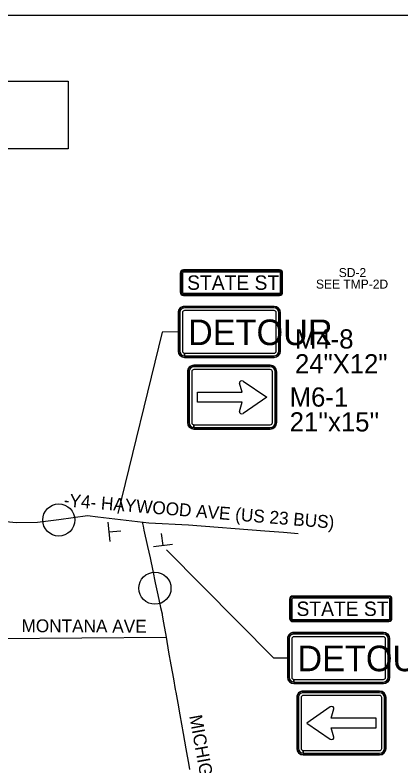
# Model space of a CAD drawing. Extents: x 886234 to 968767, y 455416 to 684046.
# Drawn here: x 925200 to 928577, y 482607 to 489183 of the extents above; entities that cross this region are included whole.
import ezdxf

# ---------------------------------------------------------------- set-up
doc = ezdxf.new("R2010")
doc.units = 0
for name, color, linetype in [('Scratch_Level_3', 7, 'Continuous'), ('TC DEV SIGN', 7, 'Continuous'), ('TC DEV SIGN BLACK 239', 7, 'Continuous'), ('TC DEV SIGN BLACK ZERO', 7, 'Continuous'), ('TC DEV SIGN ORANGE', 7, 'Continuous'), ('TC DEV SIGN WHITE', 7, 'Continuous'), ('TC LABEL TEXT', 7, 'Continuous')]:
    doc.layers.add(name, color=color, linetype=linetype)

msp = doc.modelspace()

# ---------------------------------------------------------------- linework, layer by layer
at = {"layer": 'Scratch_Level_3'}
msp.add_line((904674.3, 489183.5), (936553.3, 489183.5), dxfattribs=at)
at = {"layer": 'TC DEV SIGN'}
for p, q in [((926013.2, 484740.4), (926029.6, 484571.4)), ((926021.4, 484655.9), (926126.2, 484666.1)), ((926495.1, 484538.8), (926481.9, 484643.2)), ((926410.8, 484528.1), (926579.3, 484549.4))]:
    msp.add_line(p, q, dxfattribs=at)
at = {"layer": 'TC DEV SIGN BLACK 239'}
for p, q in [((926722.7, 486059.3), (926722.6, 485614.1)), ((926746.3, 486059.3), (926746.3, 485614.1)), ((927433.1, 486101.9), (926765.3, 486101.9)), ((927433.1, 486078.3), (926765.3, 486078.3)), ((927452, 485614.1), (927452, 486059.3)), ((927475.7, 485614.1), (927475.7, 486059.3)), ((927196.7, 485977.2), (927402, 485835.8)), ((927187.8, 485879.4), (927164.6, 485960)), ((926795.9, 485793.6), (926795.9, 485879.4)), ((926795.9, 485879.4), (927187.8, 485879.4)), ((927187.7, 485793.6), (926795.9, 485793.6)), ((927164.6, 485711.6), (927187.7, 485793.6)), ((927402, 485835.8), (927196.7, 485694.4)), ((926765.2, 485571.5), (926765.2, 485595.1)), ((926765.5, 485595.1), (927433.1, 485595.1)), ((926765.5, 485595.1), (926765.5, 485571.5)), ((926765.5, 485571.5), (927433.1, 485571.5)), ((928389.8, 483248.3), (927721.9, 483248.3)), ((928389.8, 483224.6), (927721.9, 483224.6)), ((927679.3, 483205.7), (927679.3, 482760.4)), ((927703, 483205.7), (927703, 482760.4)), ((928408.7, 482760.4), (928408.7, 483205.7)), ((928432.4, 482760.4), (928432.4, 483205.7)), ((927958.4, 483123.5), (927753.1, 482982.1)), ((927967.3, 483025.7), (927990.4, 483106.3)), ((928359.1, 483025.7), (927967.3, 483025.7)), ((928359.1, 482940), (928359.1, 483025.7)), ((927753.1, 482982.1), (927958.4, 482840.7)), ((927990.4, 482857.9), (927967.3, 482940)), ((927967.3, 482940), (928359.1, 482940)), ((927721.9, 482717.8), (927721.9, 482741.5)), ((927722.2, 482741.5), (928389.8, 482741.5)), ((927722.2, 482741.5), (927722.2, 482717.8)), ((927722.2, 482717.8), (928389.8, 482717.8))]:
    msp.add_line(p, q, dxfattribs=at)
for centre, major_axis, ratio, start_param, end_param in [((926765.3, 486059.3), (42.6, 0), 0.999865, 1.570796, 3.141593), ((926765.3, 486059.3), (18.9, 0), 0.999865, 1.570796, 3.141593), ((927433.1, 486059.3), (42.6, 0), 0.999865, 0, 1.570796), ((927433.1, 486059.3), (18.9, 0), 0.999865, 0, 1.570796), ((927184.7, 485964.6), (21.1, 0), 0.720018, 0.96961, 3.452569), ((927184.7, 485706.9), (21.1, 0), 0.720018, 2.830617, 5.313577), ((926765.2, 485614.1), (42.6, 0), 0.999865, 3.141593, 4.712389), ((926765.2, 485614.1), (18.9, 0), 0.999865, 3.141593, 4.712389), ((927433.1, 485614.1), (42.6, 0), 0.999865, 4.712389, 6.283185), ((927433.1, 485614.1), (18.9, 0), 0.999865, 4.712389, 6.283185), ((927721.9, 483205.7), (42.6, 0), 0.999865, 1.570796, 3.141593), ((927721.9, 483205.7), (18.9, 0), 0.999865, 1.570796, 3.141593), ((928389.8, 483205.7), (42.6, 0), 0.999865, 0, 1.570796), ((928389.8, 483205.7), (18.9, 0), 0.999865, 0, 1.570796), ((927970.3, 483111), (-21.1, 0), 0.720018, 2.830616, 5.313575), ((927970.3, 482853.3), (-21.1, 0), 0.720018, 0.969609, 3.452568), ((927721.9, 482760.4), (42.6, 0), 0.999865, 3.141593, 4.712389), ((927721.9, 482760.4), (18.9, 0), 0.999865, 3.141593, 4.712389), ((928389.8, 482760.4), (42.6, 0), 0.999865, 4.712389, 6.283185), ((928389.8, 482760.4), (18.9, 0), 0.999865, 4.712389, 6.283185)]:
    msp.add_ellipse(centre, major_axis=major_axis, ratio=ratio, start_param=start_param, end_param=end_param, dxfattribs=at)
at = {"layer": 'TC DEV SIGN BLACK ZERO'}
for p, q in [((926645.5, 486923.4), (926645.5, 486755.4)), ((926646.6, 486923.4), (926646.6, 486755.4)), ((926646.6, 486923.4), (926646.6, 486923.4)), ((926652.5, 486923.4), (926652.5, 486755.4)), ((926664.1, 486923.4), (926664.1, 486755.4)), ((927513.5, 486951.3), (926673.5, 486951.4)), ((926673.5, 486950.2), (926673.5, 486950.2)), ((927513.5, 486950.2), (926673.5, 486950.2)), ((927513.5, 486944.3), (926673.5, 486944.4)), ((927513.5, 486932.7), (926673.5, 486932.7)), ((927513.5, 486950.2), (927513.5, 486950.2)), ((927522.8, 486755.5), (927522.8, 486923.3)), ((927534.5, 486755.5), (927534.5, 486923.3)), ((927540.3, 486923.3), (927540.3, 486923.3)), ((927540.3, 486755.4), (927540.3, 486923.3)), ((927541.5, 486755.4), (927541.5, 486923.3)), ((926646.6, 486755.4), (926646.6, 486755.4)), ((926673.5, 486746), (927513.5, 486746)), ((926673.5, 486734.4), (927513.5, 486734.3)), ((926673.5, 486728.5), (927513.5, 486728.5)), ((926673.5, 486728.5), (926673.5, 486728.5)), ((926673.5, 486727.4), (927513.5, 486727.3)), ((927513.5, 486728.5), (927513.5, 486728.5)), ((927522.8, 486755.5), (927534.5, 486755.5)), ((927534.5, 486755.3), (927522.8, 486755.3)), ((927540.3, 486755.4), (927541.5, 486755.4)), ((927541.5, 486755.3), (927540.3, 486755.3)), ((927540.3, 486755.3), (927540.3, 486755.3)), ((927467.1, 486632), (926683, 486632)), ((926683, 486629.7), (926683, 486629.7)), ((927467.1, 486629.7), (926683, 486629.7)), ((927467.1, 486629.7), (927467.1, 486629.7)), ((926627, 486576), (926627, 486240)), ((926629.3, 486576), (926629.3, 486240)), ((926629.3, 486576), (926629.4, 486576)), ((926641, 486576), (926641, 486240)), ((926664.4, 486576), (926664.4, 486240)), ((927467.1, 486618), (926683, 486618)), ((927467.1, 486594.7), (926683, 486594.7)), ((927485.8, 486240), (927485.8, 486576)), ((927509.1, 486240), (927509.1, 486576)), ((927520.8, 486576), (927520.8, 486576)), ((927520.8, 486240), (927520.8, 486576)), ((927523.1, 486240), (927523.1, 486576)), ((926629.4, 486240), (926629.3, 486240)), ((927520.8, 486240), (927520.8, 486240)), ((926683, 486198), (926683, 486221.4)), ((926683, 486184), (926683, 486186.4)), ((926683, 486186.4), (926683, 486186.4)), ((926683.1, 486186.4), (927467.1, 486186.4)), ((926683.1, 486186.4), (926683.1, 486184)), ((926683.1, 486184), (927467.1, 486184)), ((926683.3, 486221.4), (927467.1, 486221.4)), ((926683.3, 486221.4), (926683.3, 486198)), ((926683.3, 486198), (927467.1, 486198)), ((927467.1, 486186.4), (927467.1, 486186.4)), ((927433.1, 486116.1), (926765.3, 486116.1)), ((926765.3, 486113.8), (926765.3, 486113.8)), ((927433.1, 486113.7), (926765.3, 486113.8)), ((927433.1, 486113.7), (927433.1, 486113.8)), ((926708.5, 486059.3), (926708.4, 485614.1)), ((926710.8, 486059.3), (926710.8, 485614.1)), ((926710.8, 486059.3), (926710.8, 486059.3)), ((927487.5, 486059.3), (927487.6, 486059.3)), ((927487.5, 485614.1), (927487.6, 486059.3)), ((927489.9, 485614.1), (927489.9, 486059.3)), ((926710.8, 485614.1), (926710.8, 485614.1)), ((927487.5, 485614.1), (927487.5, 485614.1)), ((926765.2, 485557.3), (926765.2, 485559.6)), ((926765.2, 485559.6), (926765.2, 485559.6)), ((926765.3, 485559.6), (927433.1, 485559.6)), ((926765.3, 485559.6), (926765.3, 485557.3)), ((926765.3, 485557.3), (927433.1, 485557.3)), ((927433.1, 485559.6), (927433.1, 485559.6)), ((927602.4, 484067.2), (927602.4, 483899.2)), ((927603.6, 484067.2), (927603.6, 483899.2)), ((927603.6, 484067.2), (927603.6, 484067.2)), ((927609.4, 484067.2), (927609.4, 483899.2)), ((927621.1, 484067.2), (927621.1, 483899.2)), ((928470.4, 484095.2), (927630.4, 484095.2)), ((927630.4, 484094), (927630.4, 484094)), ((928470.4, 484094), (927630.4, 484094)), ((928470.4, 484088.2), (927630.4, 484088.2)), ((928470.4, 484076.5), (927630.4, 484076.5)), ((928470.4, 484094), (928470.4, 484094)), ((928479.7, 483899.3), (928479.7, 484067.2)), ((928491.4, 483899.3), (928491.4, 484067.2)), ((928497.2, 484067.2), (928497.2, 484067.2)), ((928497.2, 483899.2), (928497.2, 484067.2)), ((928498.4, 483899.2), (928498.4, 484067.2)), ((927603.6, 483899.2), (927603.6, 483899.2)), ((927630.4, 483889.9), (928470.4, 483889.8)), ((927630.4, 483878.2), (928470.4, 483878.2)), ((927630.4, 483872.3), (927630.4, 483872.4)), ((927630.4, 483872.3), (928470.4, 483872.3)), ((927630.4, 483871.2), (928470.4, 483871.2)), ((928470.4, 483872.3), (928470.4, 483872.3)), ((928479.7, 483899.3), (928491.4, 483899.3)), ((928491.4, 483899.2), (928479.7, 483899.2)), ((928498.4, 483899.2), (928497.2, 483899.2)), ((928497.2, 483899.2), (928497.2, 483899.2)), ((928497.2, 483899.2), (928498.4, 483899.2)), ((928424.1, 483775.9), (927640, 483775.9)), ((927640, 483773.5), (927640, 483773.5)), ((928424.1, 483773.5), (927640, 483773.5)), ((928424.1, 483761.9), (927640, 483761.9)), ((928424.1, 483738.5), (927640, 483738.5)), ((928424.1, 483773.5), (928424.1, 483773.5)), ((927584, 483719.9), (927584, 483383.9)), ((927586.3, 483719.9), (927586.3, 483383.9)), ((927586.3, 483719.9), (927586.3, 483719.9)), ((927598, 483719.9), (927598, 483383.9)), ((927621.3, 483719.9), (927621.3, 483383.9)), ((928442.8, 483383.9), (928442.8, 483719.9)), ((928466.1, 483383.9), (928466.1, 483719.9)), ((928477.8, 483719.9), (928477.8, 483719.9)), ((928477.8, 483383.9), (928477.8, 483719.9)), ((928480.1, 483383.9), (928480.1, 483719.9)), ((927586.3, 483383.9), (927586.3, 483383.9)), ((927640, 483341.9), (927640, 483365.2)), ((927640.2, 483365.2), (928424.1, 483365.2)), ((927640.2, 483365.2), (927640.2, 483341.9)), ((927640.2, 483341.9), (928424.1, 483341.9)), ((928477.8, 483383.9), (928477.8, 483383.9)), ((927640, 483327.9), (927640, 483330.2)), ((927640, 483330.2), (927640, 483330.2)), ((927640, 483330.2), (928424.1, 483330.2)), ((927640, 483330.2), (927640, 483327.9)), ((927640, 483327.9), (928424.1, 483327.9)), ((928424.1, 483330.2), (928424.1, 483330.2)), ((928389.8, 483262.5), (927721.9, 483262.5)), ((927721.9, 483260.1), (927721.9, 483260.1)), ((928389.8, 483260.1), (927721.9, 483260.1)), ((928389.8, 483260.1), (928389.8, 483260.1)), ((927665.1, 483205.7), (927665.1, 482760.4)), ((927667.5, 483205.7), (927667.5, 482760.4)), ((927667.5, 483205.7), (927667.5, 483205.7)), ((928444.2, 483205.7), (928444.2, 483205.7)), ((928444.2, 482760.4), (928444.2, 483205.7)), ((928446.6, 482760.4), (928446.6, 483205.7)), ((927667.5, 482760.4), (927667.5, 482760.4)), ((928444.2, 482760.4), (928444.2, 482760.4)), ((927721.9, 482703.6), (927721.9, 482706)), ((927721.9, 482706), (927721.9, 482706)), ((927722, 482706), (928389.8, 482706)), ((927722, 482706), (927722, 482703.6)), ((927722, 482703.6), (928389.8, 482703.6)), ((928389.8, 482706), (928389.8, 482706))]:
    msp.add_line(p, q, dxfattribs=at)
for centre, major_axis, start_param, end_param in [((926673.5, 486923.4), (0, 28), 0, 1.570796), ((926673.5, 486923.4), (0, 26.8), 0, 1.570796), ((926673.5, 486923.4), (0, 21), 0, 1.570796), ((926673.5, 486923.4), (0, 9.33), 0, 1.570796), ((927513.5, 486923.3), (0, 28), 4.712389, 6.283185), ((927513.5, 486923.3), (0, 26.8), 4.712389, 6.283185), ((927513.5, 486923.3), (0, 21), 4.712389, 6.283185), ((927513.5, 486923.3), (0, 9.33), 4.712389, 6.283185), ((926673.5, 486755.4), (0, 28), 1.570796, 3.141593), ((926673.5, 486755.4), (0, 26.8), 1.570796, 3.141593), ((926673.5, 486755.4), (0, 21), 1.570796, 3.141593), ((926673.5, 486755.4), (0, 9.33), 1.570796, 3.141593), ((927513.5, 486755.3), (0, 21), 3.141593, 4.712389), ((927513.5, 486755.3), (0, 9.33), 3.141593, 4.712389), ((927513.5, 486755.3), (0, 28), 3.141593, 4.712389), ((927513.5, 486755.3), (0, 26.8), 3.141593, 4.712389), ((926683, 486576), (56, 0), 1.570796, 3.141593), ((926683, 486576), (53.7, 0), 1.570796, 3.141593), ((927467.1, 486576), (56, 0), 0, 1.570796), ((927467.1, 486576), (53.7, 0), 0, 1.570796), ((926683, 486576), (42, 0), 1.570796, 3.141593), ((926683, 486576), (18.7, 0), 1.570796, 3.141593), ((927467.1, 486576), (42, 0), 0, 1.570796), ((927467.1, 486576), (18.7, 0), 0, 1.570796), ((926683, 486240), (56, 0), 3.141593, 4.712389), ((926683, 486240), (53.7, 0), 3.141593, 4.712389), ((926683, 486240), (42, 0), 3.141593, 4.712389), ((926683, 486240), (18.7, 0), 3.141593, 4.712389), ((927467.1, 486240), (42, 0), 4.712389, 6.283185), ((927467.1, 486240), (18.7, 0), 4.712389, 6.283185), ((927467.1, 486240), (56, 0), 4.712389, 6.283185), ((927467.1, 486240), (53.7, 0), 4.712389, 6.283185), ((926765.3, 486059.3), (56.8, 0), 1.570796, 3.141593), ((926765.3, 486059.3), (54.4, 0), 1.570796, 3.141593), ((927433.1, 486059.3), (56.8, 0), 0, 1.570796), ((927433.1, 486059.3), (54.4, 0), 0, 1.570796), ((926765.2, 485614.1), (56.8, 0), 3.141593, 4.712389), ((926765.2, 485614.1), (54.4, 0), 3.141593, 4.712389), ((927433.1, 485614.1), (56.8, 0), 4.712389, 6.283185), ((927433.1, 485614.1), (54.4, 0), 4.712389, 6.283185), ((927630.4, 484067.2), (0, 28), 0, 1.570796), ((927630.4, 484067.2), (0, 26.8), 0, 1.570796), ((927630.4, 484067.2), (0, 21), 0, 1.570796), ((927630.4, 484067.2), (0, 9.33), 0, 1.570796), ((928470.4, 484067.2), (0, 28), 4.712389, 6.283185), ((928470.4, 484067.2), (0, 26.8), 4.712389, 6.283185), ((928470.4, 484067.2), (0, 21), 4.712389, 6.283185), ((928470.4, 484067.2), (0, 9.33), 4.712389, 6.283185), ((927630.4, 483899.2), (0, 28), 1.570796, 3.141593), ((927630.4, 483899.2), (0, 26.8), 1.570796, 3.141593), ((927630.4, 483899.2), (0, 21), 1.570796, 3.141593), ((927630.4, 483899.2), (0, 9.33), 1.570796, 3.141593), ((928470.4, 483899.2), (0, 21), 3.141593, 4.712389), ((928470.4, 483899.2), (0, 9.33), 3.141593, 4.712389), ((928470.4, 483899.2), (0, 28), 3.141593, 4.712389), ((928470.4, 483899.2), (0, 26.8), 3.141593, 4.712389), ((927640, 483719.9), (56, 0), 1.570796, 3.141593), ((927640, 483719.9), (53.7, 0), 1.570796, 3.141593), ((927640, 483719.9), (42, 0), 1.570796, 3.141593), ((927640, 483719.9), (18.7, 0), 1.570796, 3.141593), ((928424.1, 483719.9), (56, 0), 0, 1.570796), ((928424.1, 483719.9), (53.7, 0), 0, 1.570796), ((928424.1, 483719.9), (42, 0), 0, 1.570796), ((928424.1, 483719.9), (18.7, 0), 0, 1.570796), ((927640, 483383.9), (56, 0), 3.141593, 4.712389), ((927640, 483383.9), (53.7, 0), 3.141593, 4.712389), ((927640, 483383.9), (42, 0), 3.141593, 4.712389), ((927640, 483383.9), (18.7, 0), 3.141593, 4.712389), ((928424.1, 483383.9), (42, 0), 4.712389, 6.283185), ((928424.1, 483383.9), (18.7, 0), 4.712389, 6.283185), ((928424.1, 483383.9), (56, 0), 4.712389, 6.283185), ((928424.1, 483383.9), (53.7, 0), 4.712389, 6.283185), ((927721.9, 483205.7), (56.8, 0), 1.570796, 3.141593), ((927721.9, 483205.7), (54.4, 0), 1.570796, 3.141593), ((928389.8, 483205.7), (56.8, 0), 0, 1.570796), ((928389.8, 483205.7), (54.4, 0), 0, 1.570796), ((927721.9, 482760.4), (56.8, 0), 3.141593, 4.712389), ((927721.9, 482760.4), (54.4, 0), 3.141593, 4.712389), ((928389.8, 482760.4), (56.8, 0), 4.712389, 6.283185), ((928389.8, 482760.4), (54.4, 0), 4.712389, 6.283185)]:
    msp.add_ellipse(centre, major_axis=major_axis, ratio=0.999865, start_param=start_param, end_param=end_param, dxfattribs=at)
at = {"layer": 'TC DEV SIGN ORANGE'}
for p, q in [((926645.5, 486923.4), (926645.5, 486755.4)), ((927513.5, 486951.3), (926673.5, 486951.4)), ((927541.5, 486755.3), (927541.5, 486923.3)), ((926673.5, 486727.4), (927513.5, 486727.3)), ((927467.1, 486632), (926683, 486632)), ((926627, 486576), (926627, 486240)), ((927523.1, 486240), (927523.1, 486576)), ((926683, 486184), (927467.1, 486184)), ((927602.4, 484067.2), (927602.4, 483899.2)), ((928470.4, 484095.2), (927630.4, 484095.2)), ((928498.4, 483899.2), (928498.4, 484067.2)), ((927630.4, 483871.2), (928470.4, 483871.2)), ((928424.1, 483775.9), (927640, 483775.9)), ((927584, 483719.9), (927584, 483383.9)), ((928480.1, 483383.9), (928480.1, 483719.9)), ((927640, 483327.9), (928424.1, 483327.9))]:
    msp.add_line(p, q, dxfattribs=at)
for centre, major_axis, start_param, end_param in [((926673.5, 486923.4), (0, 28), 0, 1.570796), ((927513.5, 486923.3), (0, 28), 4.712389, 6.283185), ((926673.5, 486755.4), (0, 28), 1.570796, 3.141593), ((927513.5, 486755.3), (0, 28), 3.141593, 4.712389), ((926683, 486576), (56, 0), 1.570796, 3.141593), ((927467.1, 486576), (56, 0), 0, 1.570796), ((926683, 486240), (56, 0), 3.141593, 4.712389), ((927467.1, 486240), (56, 0), 4.712389, 6.283185), ((927630.4, 484067.2), (0, 28), 0, 1.570796), ((928470.4, 484067.2), (0, 28), 4.712389, 6.283185), ((927630.4, 483899.2), (0, 28), 1.570796, 3.141593), ((928470.4, 483899.2), (0, 28), 3.141593, 4.712389), ((927640, 483719.9), (56, 0), 1.570796, 3.141593), ((928424.1, 483719.9), (56, 0), 0, 1.570796), ((927640, 483383.9), (56, 0), 3.141593, 4.712389), ((928424.1, 483383.9), (56, 0), 4.712389, 6.283185)]:
    msp.add_ellipse(centre, major_axis=major_axis, ratio=0.999865, start_param=start_param, end_param=end_param, dxfattribs=at)
at = {"layer": 'TC DEV SIGN WHITE'}
for p, q in [((927433.1, 486116.1), (926765.3, 486116.1)), ((926708.5, 486059.3), (926708.4, 485614.1)), ((927489.9, 485614.1), (927489.9, 486059.3)), ((926765.2, 485557.3), (927433.1, 485557.3)), ((928389.8, 483262.5), (927721.9, 483262.5)), ((927665.1, 483205.7), (927665.1, 482760.4)), ((928446.6, 482760.4), (928446.6, 483205.7)), ((927721.9, 482703.6), (928389.8, 482703.6))]:
    msp.add_line(p, q, dxfattribs=at)
for centre, start_param, end_param in [((926765.3, 486059.3), 1.570796, 3.141593), ((927433.1, 486059.3), 0, 1.570796), ((926765.2, 485614.1), 3.141593, 4.712389), ((927433.1, 485614.1), 4.712389, 6.283185), ((927721.9, 483205.7), 1.570796, 3.141593), ((928389.8, 483205.7), 0, 1.570796), ((927721.9, 482760.4), 3.141593, 4.712389), ((928389.8, 482760.4), 4.712389, 6.283185)]:
    msp.add_ellipse(centre, major_axis=(56.8, 0), ratio=0.999865, start_param=start_param, end_param=end_param, dxfattribs=at)
at = {"layer": 'TC LABEL TEXT'}
msp.add_line((925038.5, 483722.9), (926522.5, 483733.5), dxfattribs=at)
msp.add_lwpolyline([(921268.8, 488603.4), (925666, 488603.4), (925666, 488012.8), (921268.8, 488012.8)], close=True, dxfattribs=at)
for points in [[(926627, 486408), (926486.6, 486407.1), (926098.5, 484818)], [(927677.1, 484640.5), (927549.4, 484651), (927385, 484664.3), (926717, 484714.2), (926371, 484734.2), (925925.5, 484787), (925835.4, 484798.7), (925582.4, 484760.9), (925396.4, 484737.6), (925210.3, 484734.7), (925123.1, 484743.4), (924952.9, 484800)], [(926313.7, 484741), (926318, 484719.1), (926320.6, 484706.9), (926327.1, 484671.6), (926360.3, 484529.4), (926383.7, 484430), (926404.3, 484315.6), (926426.1, 484210.3), (926449.6, 484106.1), (926473.6, 483995.1), (926486.5, 483938.6), (926488.3, 483926.2)], [(927584, 483551.9), (927464, 483551.9), (926524.3, 484498.8)], [(926488.3, 483926.2), (926497.7, 483860.9), (926522.5, 483733.5), (926543.1, 483603), (926563.7, 483492.1), (926585.7, 483370.7), (926602.2, 483276.4), (926606.6, 483252.6)], [(926606.6, 483252.6), (926624.6, 483155.2), (926643.3, 483053.2), (926669.9, 482891.6), (926693.5, 482757.8), (926720, 482614.3), (926727.1, 482574.7)]]:
    msp.add_lwpolyline(points, dxfattribs=at)
for centre in [(925582.4, 484760.9), (925582.4, 484760.9), (926424.1, 484163.2), (926424.1, 484163.2)]:
    msp.add_circle(centre, 140.6, dxfattribs=at)

# ---------------------------------------------------------------- texts
at = {"layer": 'TC DEV SIGN BLACK ZERO'}
for s, height, p in [('STATE ST', 126, (926706.2, 486776.6)), ('DETOUR', 224, (926714.1, 486292.6)), ('STATE ST', 126, (927663.1, 483920.4)), ('DETOUR', 224, (927671.1, 483436.4))]:
    msp.add_text(s, height=height, dxfattribs=at).set_placement(p)
for s, p in [('M4-8', (927649.9, 486262.5)), ('24"X12"', (927649.9, 486045.2)), ('M6-1', (927603.3, 485753.8)), ("21''x15''", (927603.3, 485536.5))]:
    msp.add_text(s, height=168, rotation=360, dxfattribs=at).set_placement(p)
at = {"layer": 'TC LABEL TEXT'}
for s, p in [('SD-2', (928032.6, 486888.5)), ('SEE TMP-2D', (927833.1, 486787.4))]:
    msp.add_text(s, height=78.75, dxfattribs=at).set_placement(p)
for s, rotation, p in [('-Y4- HAYWOOD AVE (US 23 BUS)', 355.23978, (925623.3, 484881.2)), ('MONTANA AVE', 359.76282, (925256.4, 483778.8)), ('MICHIGAN ST', 280.34625, (926723.7, 483044))]:
    msp.add_text(s, height=112.5, rotation=rotation, dxfattribs=at).set_placement(p)

doc.saveas('drawing.dxf')
